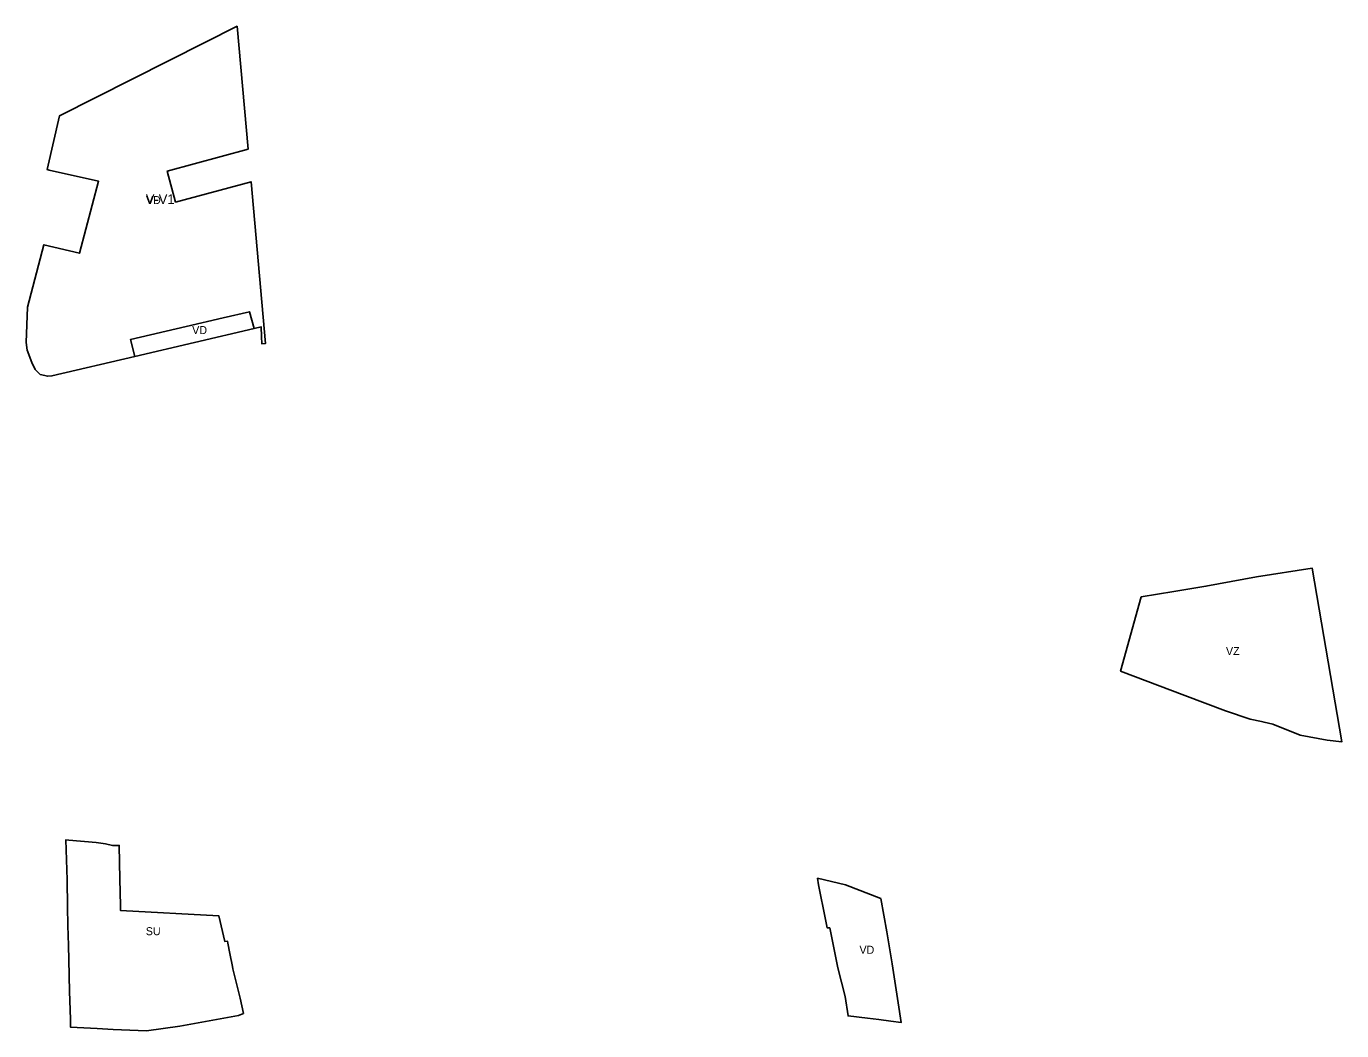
# Model space of a CAD drawing. Extents: x -532031 to -530019, y -1180236 to -1177276.
# Drawn here: x -532031 to -531209, y -1178486 to -1177859 of the extents above; entities that cross this region are included whole.
import ezdxf

# ---------------------------------------------------------------- set-up
doc = ezdxf.new("R2010")
doc.units = 0
for name, color, linetype in [('90480013', 7, 'Continuous'), ('90590013', 7, 'Continuous'), ('90590023', 7, 'Continuous'), ('90600013', 7, 'Continuous'), ('ID_navrh', 7, 'Continuous')]:
    doc.layers.add(name, color=color, linetype=linetype)

msp = doc.modelspace()

# ---------------------------------------------------------------- linework, layer by layer
at = {"layer": '90480013'}
msp.add_lwpolyline([(-531981.1043, -1178369.82445), (-531976.8043, -1178370.74345), (-531972.5833, -1178370.74345), (-531972.1303, -1178391.76645), (-531971.7473, -1178408.31345), (-531971.7473, -1178411.39245), (-531910.3083, -1178414.75845), (-531906.4913, -1178430.77045), (-531904.9533, -1178430.53145), (-531904.6723, -1178431.80145), (-531903.4343, -1178438.26145), (-531901.8593, -1178446.33445), (-531901.6193, -1178447.73045), (-531897.0773, -1178466.22745), (-531894.9673, -1178475.68145), (-531898.0073, -1178477.00845), (-531934.6823, -1178483.55345), (-531955.6063, -1178486.48745), (-531976.3063, -1178485.81045), (-531986.4303, -1178485.13345), (-532003.0803, -1178484.23045), (-532003.0803, -1178479.26545), (-532003.7043, -1178461.93145), (-532004.1143, -1178442.16845), (-532004.2623, -1178433.24445), (-532004.7073, -1178420.74945), (-532004.8563, -1178408.99845), (-532005.0163, -1178392.15645), (-532005.8403, -1178367.13645), (-532004.0613, -1178367.35545), (-531987.0563, -1178368.92845)], close=True, dxfattribs=at)
at = {"layer": '90590013'}
for points in [[(-531888.2813, -1178047.78945), (-531962.7363, -1178065.22045), (-531965.5863, -1178054.60345), (-531930.8363, -1178046.48945), (-531907.7213, -1178041.16445), (-531891.1453, -1178037.20945)], [(-531496.8793, -1178403.96645), (-531493.0223, -1178424.70045), (-531489.7253, -1178444.74745), (-531486.0123, -1178469.03445), (-531484.0143, -1178481.26245), (-531490.4323, -1178480.48645), (-531498.0103, -1178479.57045), (-531505.1923, -1178478.70245), (-531517.1883, -1178477.25245), (-531518.9873, -1178465.02445), (-531523.7043, -1178447.15045), (-531528.7123, -1178422.29345), (-531530.2943, -1178422.29345), (-531531.3243, -1178416.97845), (-531535.6173, -1178395.44645), (-531536.2743, -1178391.25045), (-531518.8663, -1178395.27845)]]:
    msp.add_lwpolyline(points, close=True, dxfattribs=at)
at = {"layer": '90590023'}
msp.add_lwpolyline([(-531892.0483, -1177935.76845), (-531942.5603, -1177949.40145), (-531937.3493, -1177968.71045), (-531890.2323, -1177955.99345), (-531881.1593, -1178057.02345), (-531883.5303, -1178057.25145), (-531883.6763, -1178052.70245), (-531883.8673, -1178046.75645), (-531888.2813, -1178047.78945), (-531891.1453, -1178037.20945), (-531907.7213, -1178041.16445), (-531930.8363, -1178046.48945), (-531965.5863, -1178054.60345), (-531962.7363, -1178065.22045), (-532014.6303, -1178077.36945), (-532017.2153, -1178077.52145), (-532021.9303, -1178076.45745), (-532024.9713, -1178073.41445), (-532027.2523, -1178069.00345), (-532029.9963, -1178061.25345), (-532030.6043, -1178056.38545), (-532029.8433, -1178034.48045), (-532019.6403, -1177995.37945), (-531997.4373, -1178000.70345), (-531985.4293, -1177955.73145), (-532016.3003, -1177948.73445), (-532017.5013, -1177948.46245), (-532009.8633, -1177914.77145), (-531919.1213, -1177869.10445), (-531898.9523, -1177858.90145)], close=True, dxfattribs=at)
at = {"layer": '90600013'}
msp.add_lwpolyline([(-531222.9713, -1178223.05245), (-531208.8803, -1178306.09445), (-531217.9073, -1178304.99045), (-531234.8613, -1178301.89845), (-531251.8143, -1178295.05145), (-531257.3183, -1178293.72645), (-531259.0803, -1178293.28445), (-531266.1263, -1178291.73845), (-531281.5423, -1178286.52645), (-531306.9273, -1178276.97845), (-531347.0433, -1178261.80745), (-531334.1103, -1178215.47745), (-531313.6463, -1178212.00845), (-531293.6743, -1178208.82545), (-531262.1623, -1178202.95445), (-531227.3753, -1178197.43345)], close=True, dxfattribs=at)

# ---------------------------------------------------------------- texts
at = {"layer": '90480013'}
msp.add_text('SU', height=5, rotation=359.99999999, dxfattribs=at).set_placement((-531955.96317, -1178426.81195))
at = {"layer": '90590013'}
for rotation, p in [(359.99999989, (-531926.99366, -1178051.21495)), (359.99999996, (-531510.1443, -1178438.41438))]:
    msp.add_text('VD', height=5, rotation=rotation, dxfattribs=at).set_placement(p)
at = {"layer": '90590023'}
msp.add_text('VD', height=5, rotation=0.00000004, dxfattribs=at).set_placement((-531955.8818, -1177969.97105))
at = {"layer": '90600013'}
msp.add_text('VZ', height=5, rotation=0.00000003, dxfattribs=at).set_placement((-531281.16952, -1178251.76395))
at = {"layer": 'ID_navrh'}
msp.add_text('V-V1', height=6, rotation=360, dxfattribs=at).set_placement((-531955.8818, -1177969.97105))

doc.saveas('drawing.dxf')
